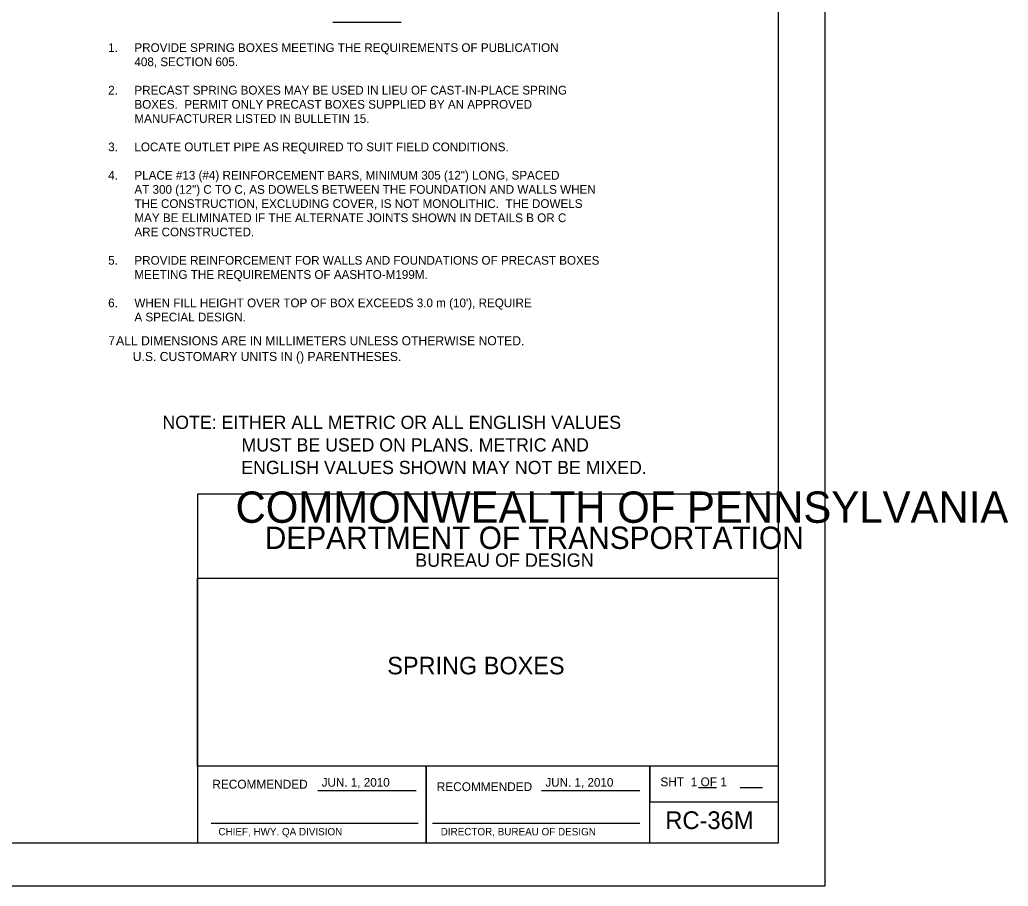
# Model space of a CAD drawing. Extents: x 638443 to 639347, y 298405 to 298999.
# Drawn here: x 639007.2 to 639347.4, y 298405 to 298703.3 of the extents above; entities that cross this region are included whole.
import ezdxf

# ---------------------------------------------------------------- set-up
doc = ezdxf.new("R2010")
doc.units = 0
for name, color, linetype in [('1', 7, 'Continuous'), ('2', 7, 'Continuous'), ('40', 7, 'Continuous'), ('PLT-BNDY', 7, 'Continuous')]:
    doc.layers.add(name, color=color, linetype=linetype)

msp = doc.modelspace()

# ---------------------------------------------------------------- linework, layer by layer
at = {"layer": '1'}
for p, q in [((639114.98, 298702.53), (639138.48, 298702.53)), ((639109.77, 298437.94), (639143.66, 298437.94)), ((639186.77, 298437.94), (639220.64, 298437.94)), ((639240.82, 298438.93), (639246.96, 298438.93)), ((639255.16, 298438.93), (639262.8, 298438.93)), ((639073.07, 298426.73), (639144.32, 298426.73)), ((639149.24, 298426.73), (639220.58, 298426.73))]:
    msp.add_line(p, q, dxfattribs=at)
msp.add_lwpolyline([(639268.31, 298419.95), (639268.31, 298983.95), (638482.31, 298983.95), (638482.31, 298419.95), (639268.31, 298419.95), (639268.31, 298446.31), (639068.31, 298446.31), (639068.31, 298510.99), (639268.31, 298510.99), (639268.31, 298539.95), (639068.31, 298539.95), (639068.31, 298419.95), (639147.11, 298419.95), (639147.11, 298446.31), (639147.11, 298419.95), (639224.11, 298419.95), (639224.11, 298446.31), (639224.11, 298434), (639268.31, 298434)], dxfattribs=at)
at = {"layer": 'PLT-BNDY'}
msp.add_lwpolyline([(638443.31, 298998.95), (639284.31, 298998.95), (639284.31, 298404.95), (638443.31, 298404.95)], close=True, dxfattribs=at)

# ---------------------------------------------------------------- texts
at = {"layer": '1'}
for s, height, p in [('1.  ', 3, (639037.62, 298692.22)), ('PROVIDE SPRING BOXES MEETING THE REQUIREMENTS OF PUBLICATION', 3, (639046.65, 298692.22)), ('408, SECTION 605.', 3, (639046.65, 298687.34)), ('2.  ', 3, (639037.62, 298677.57)), ('PRECAST SPRING BOXES MAY BE USED IN LIEU OF CAST-IN-PLACE SPRING', 3, (639046.65, 298677.57)), ('BOXES.  PERMIT ONLY PRECAST BOXES SUPPLIED BY AN APPROVED', 3, (639046.65, 298672.69)), ('MANUFACTURER LISTED IN BULLETIN 15.', 3, (639046.65, 298667.81)), ('3.  ', 3, (639037.62, 298658.04)), ('LOCATE OUTLET PIPE AS REQUIRED TO SUIT FIELD CONDITIONS.', 3, (639046.65, 298658.04)), ('4.  ', 3, (639037.62, 298648.28)), ('PLACE #13 (#4) REINFORCEMENT BARS, MINIMUM 305 (12") LONG, SPACED', 3, (639046.65, 298648.28)), ('AT 300 (12") C TO C, AS DOWELS BETWEEN THE FOUNDATION AND WALLS WHEN', 3, (639046.65, 298643.39)), ('THE CONSTRUCTION, EXCLUDING COVER, IS NOT MONOLITHIC.  THE DOWELS', 3, (639046.65, 298638.51)), ('MAY BE ELIMINATED IF THE ALTERNATE JOINTS SHOWN IN DETAILS B OR C', 3, (639046.65, 298633.63)), ('ARE CONSTRUCTED.', 3, (639046.65, 298628.74)), ('5.  ', 3, (639037.62, 298618.98)), ('PROVIDE REINFORCEMENT FOR WALLS AND FOUNDATIONS OF PRECAST BOXES', 3, (639046.65, 298618.98)), ('MEETING THE REQUIREMENTS OF AASHTO-M199M.', 3, (639046.65, 298614.1)), ('6.  ', 3, (639037.62, 298604.33)), ("WHEN FILL HEIGHT OVER TOP OF BOX EXCEEDS 3.0 m (10'), REQUIRE", 3, (639046.65, 298604.33)), ('A SPECIAL DESIGN.', 3, (639046.65, 298599.45)), ('7.', 3, (639037.71, 298591.35)), ('COMMONWEALTH OF PENNSYLVANIA', 10.7834, (639081.46, 298530.1)), ('DEPARTMENT OF TRANSPORTATION', 7.6843, (639091.52, 298521.1)), ('BUREAU OF DESIGN', 4.6221, (639143.29, 298514.94)), ('SPRING BOXES', 6.04, (639133.69, 298477.92)), ('RECOMMENDED', 3.048, (639073.47, 298438.55)), ('JUN. 1, 2010', 3, (639111.11, 298439.23)), ('RECOMMENDED', 3.048, (639150.72, 298437.71)), ('JUN. 1, 2010', 3, (639188.11, 298439.23)), ('SHT  1 OF 1', 3.048, (639227.71, 298439.38)), ('APPROVED', 0.0192, (639111.33, 298437.89)), ('RC-36M', 6.096, (639229.4, 298424.65)), ('CHIEF, HWY. QA DIVISION', 2.54, (639075.55, 298422.48)), ('DIRECTOR, BUREAU OF DESIGN', 2.54, (639152.08, 298422.48))]:
    msp.add_text(s, height=height, dxfattribs=at).set_placement(p)
at = {"layer": '2'}
msp.add_text('   ALL DIMENSIONS ARE IN MILLIMETERS UNLESS OTHERWISE NOTED.', height=3.126, dxfattribs=at).set_placement((639036.88, 298591.23))
at = {"layer": '40'}
for s, height, p in [('U.S. CUSTOMARY UNITS IN () PARENTHESES.', 3.126, (639046.08, 298585.8)), ('NOTE: EITHER ALL METRIC OR ALL ENGLISH VALUES', 4.5587, (639056.3, 298562.42)), ('MUST BE USED ON PLANS. METRIC AND', 4.5587, (639083.52, 298554.65)), ('ENGLISH VALUES SHOWN MAY NOT BE MIXED.', 4.5587, (639083.45, 298546.88))]:
    msp.add_text(s, height=height, dxfattribs=at).set_placement(p)

doc.saveas('drawing.dxf')
